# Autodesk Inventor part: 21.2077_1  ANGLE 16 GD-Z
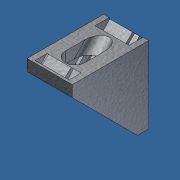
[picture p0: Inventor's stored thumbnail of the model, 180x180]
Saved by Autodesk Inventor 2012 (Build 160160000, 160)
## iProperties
Created: 2014-03
Part Number: 21.2077_1  ANGLE 16 GD-Z
Material: Aluminum-6061
Document SubType Name: Modeling
Designer: Admin
Density: 2.71 g/cm^3
Mass: 10.4203 g
Surface Area: 34.2711 cm^2
Volume: 3.84511 cm^3
Description: ANGLE 16 GD-Z
Stock Number: 21.2077_1 ANGLE 16 GD-Z
Translation Standard: STEP AP214IS
FileName: C:\AAAAINTERNET\UPLOAD\21.2077_1  ANGLE 16 GD-Z.stp
PreProcessor: Autodesk Inventor 2012
PostProcessor: Build: 160, Release: 2012 RTM - Date: Tue 03/01/2011
Sent Units: inch
Uncertainty: 0.00039370078740199997
Author: Admin
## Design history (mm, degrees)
node "3NEW1"
node "Base1"
body "Solid1"
